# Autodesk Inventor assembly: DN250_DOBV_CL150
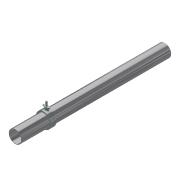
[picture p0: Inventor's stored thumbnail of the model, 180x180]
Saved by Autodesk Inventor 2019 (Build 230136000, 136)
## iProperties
Created: 2019-09
Part Number: DN250_DOBV_CL150
Document SubType Name: Assembly
Designer: Admin
Author: Admin
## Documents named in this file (9)
- E:\Chaitanya\CVP\IVDC 2019\Technical\Geometry\Base Model\CAD Files and Guidelines document - IVDC 2019\Assembly File\DN250_DOBV_CL150.iam
- E:\Chaitanya\CVP\IVDC 2019\Technical\Geometry\Base Model\CAD Files and Guidelines document - IVDC 2019\Assembly File\Valve_body.ipt
- E:\Chaitanya\CVP\IVDC 2019\Technical\Geometry\Base Model\CAD Files and Guidelines document - IVDC 2019\Assembly File\Seat.ipt
- E:\Chaitanya\CVP\IVDC 2019\Technical\Geometry\Base Model\CAD Files and Guidelines document - IVDC 2019\Assembly File\Seat_retainer.ipt
- E:\Chaitanya\CVP\IVDC 2019\Technical\Geometry\Base Model\CAD Files and Guidelines document - IVDC 2019\Assembly File\Shaft.ipt
- E:\Chaitanya\CVP\IVDC 2019\Technical\Geometry\Base Model\CAD Files and Guidelines document - IVDC 2019\Assembly File\Valve_disc.ipt
- E:\Chaitanya\CVP\IVDC 2019\Technical\Geometry\Base Model\CAD Files and Guidelines document - IVDC 2019\Assembly File\Pins.ipt
- E:\Chaitanya\CVP\IVDC 2019\Technical\Geometry\Base Model\CAD Files and Guidelines document - IVDC 2019\Assembly File\Inlet Pipe.ipt
- E:\Chaitanya\CVP\IVDC 2019\Technical\Geometry\Base Model\CAD Files and Guidelines document - IVDC 2019\Assembly File\Outlet Pipe.ipt
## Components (9 placed, 8 different names)
1. Valve_body:1 — Flush:1, Flush:2, Flush:3, Mate:1, Flush:4, Mate:4, Flush:5, Mate:8, Flush:9, Mate:9, Mate:12, Mate:13
2. Seat:1 — Mate:1, Flush:4
3. Seat_retainer:1 — Mate:8, Flush:9, Mate:9, Mate:14, Mate:15
4. Shaft:1 — Mate:4, Flush:5, Mate:5, Flush:6
5. Valve_disc:1 — Mate:5, Flush:6, Mate:6, Flush:7, Mate:7, Flush:8
6. Pins:1 — Mate:6, Flush:7
7. Pins:2 — Mate:7, Flush:8
8. Outlet Pipe:1 — Mate:12, Mate:13
9. Inlet Pipe:1 — Mate:14, Mate:15
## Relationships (20: Mate 11, Flush 9)
- Flush:1: Valve_body:1
- Flush:2: Valve_body:1
- Flush:3: Valve_body:1
- Mate:1: Valve_body:1 ↔ Seat:1
- Flush:4: Valve_body:1 ↔ Seat:1
- Mate:4: Valve_body:1 ↔ Shaft:1
- Flush:5: Valve_body:1 ↔ Shaft:1
- Mate:5: Shaft:1 ↔ Valve_disc:1
- Flush:6: Shaft:1 ↔ Valve_disc:1
- Mate:6: Valve_disc:1 ↔ Pins:1
- Flush:7: Valve_disc:1 ↔ Pins:1
- Mate:7: Valve_disc:1 ↔ Pins:2
- Flush:8: Valve_disc:1 ↔ Pins:2
- Mate:8: Valve_body:1 ↔ Seat_retainer:1
- Flush:9: Valve_body:1 ↔ Seat_retainer:1
- Mate:9: Valve_body:1 ↔ Seat_retainer:1
- Mate:12: Valve_body:1 ↔ Outlet Pipe:1
- Mate:13: Valve_body:1 ↔ Outlet Pipe:1
- Mate:14: Seat_retainer:1 ↔ Inlet Pipe:1
- Mate:15: Seat_retainer:1 ↔ Inlet Pipe:1
